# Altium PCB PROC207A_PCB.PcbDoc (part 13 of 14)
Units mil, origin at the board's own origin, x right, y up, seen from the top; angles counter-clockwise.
Board outline 4094.49 x 3724.79 mil, 8 copper layers (Top Layer, L2_GND1, L3_SIG1, L4_PWR1, L5_PWR2, L6_SIG2, L7_GND2, Bottom Layer), stack 58.1 mil thick; 584 components, 399 nets, 8440 pads, 5258 vias.
Unrouted connection lines stored in the file: 9.
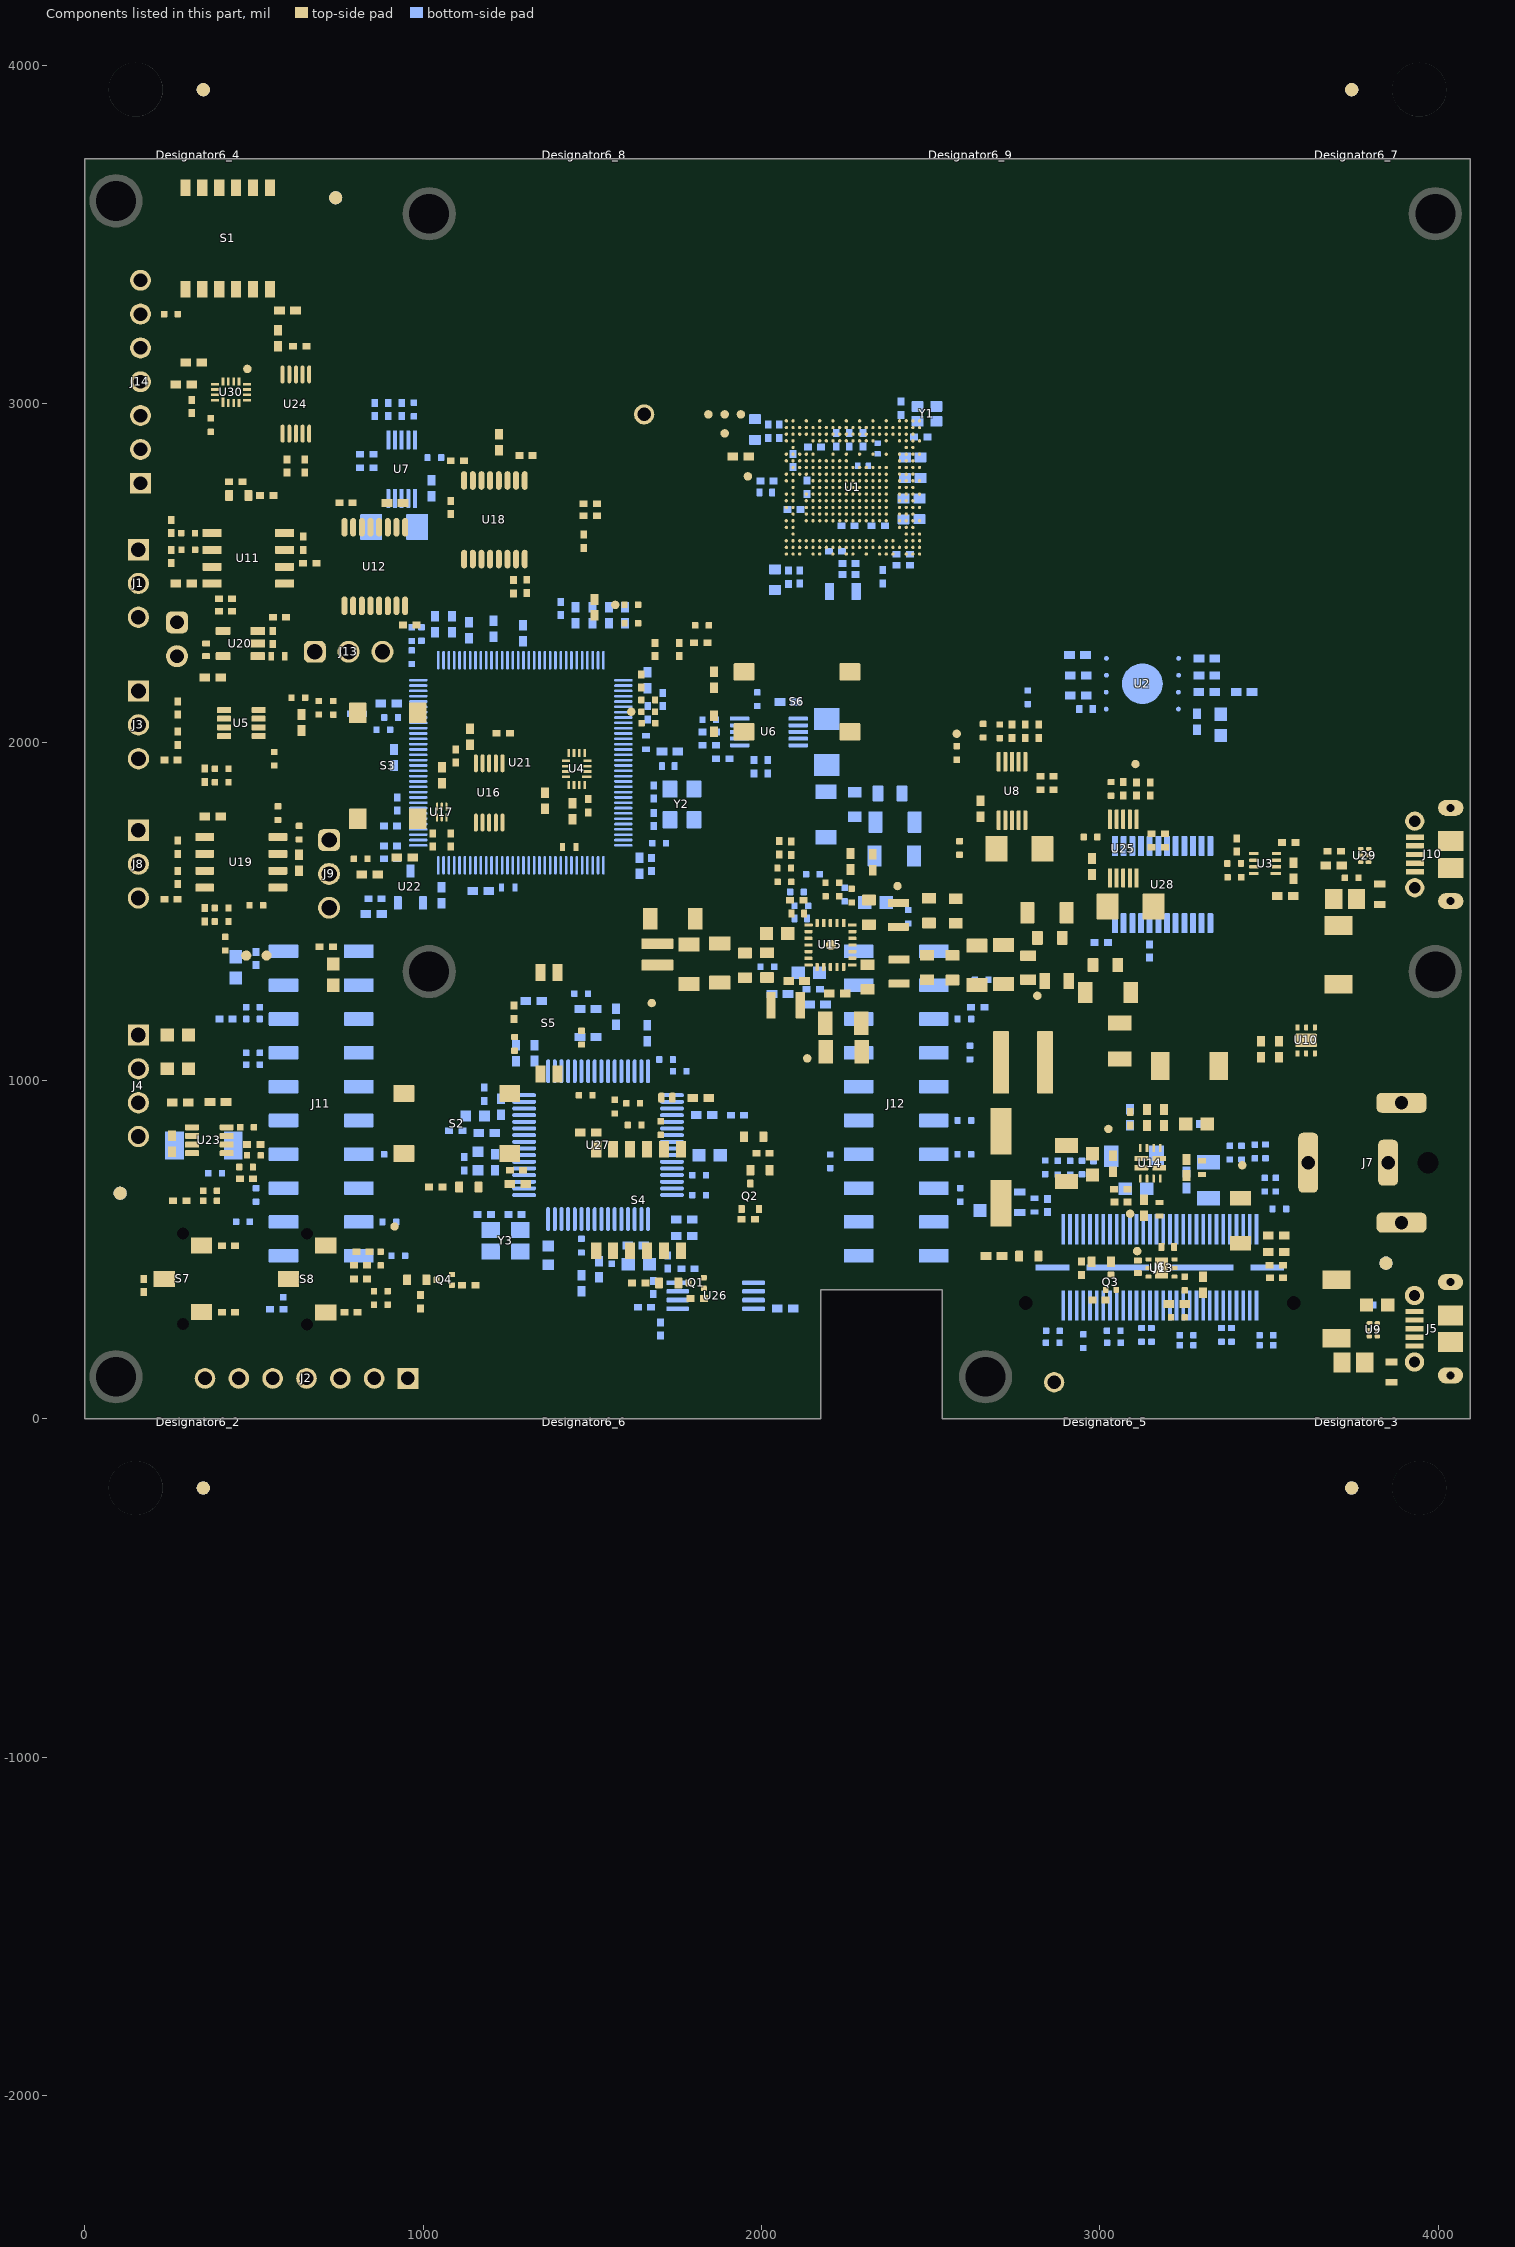
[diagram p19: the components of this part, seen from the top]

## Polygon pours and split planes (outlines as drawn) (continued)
NetC43_1 on Top Layer "NONET_L08_P-001" (solid, remove dead copper, pour order 55): 3167.19,1136 cw(c3167.19,1096.15) 3207.04,1096.15 3207.05,983.06 cw(c3183.73,983.06) 3183.73,959.75 2809.67,959.75 2809.67,1149.2 2981.83,1149.2 2995.03,1136
PMIC_B1_SW on Top Layer "NONET_L08_P-001" (solid, remove dead copper, pour order 63): 19 vertices, not listed, extent 2098.68,1183.02 2170.1,1345.39
VCC_CAN_3V3 on Top Layer "NONET_L08_P-001" (solid, remove dead copper, pour order 65): 1742.21,1383.92 1742.21,1508.92 1735.76,1515.37 1627.61,1515.37 1617.84,1505.6 1617.84,1390.27 1624.19,1383.92
PMIC_LS_3V3 on Top Layer "NONET_L08_P-001" (solid, remove dead copper, pour order 68): 18 vertices, not listed, extent 2107.76,1454.29 2200.61,1596.57
PMIC_OUT_3V3 on Top Layer "NONET_L08_P-001" (solid, remove dead copper, pour order 70): 2158.71,1458.43 2160.71,1456.43 2167.75,1456.43 2170.91,1459.59 2170.91,1478.69 2175.78,1483.56 2175.78,1498.59 2174.36,1500.01 2151.55,1500.01 2151.55,1488.94 2158.71,1481.78
REG_1V2 on Top Layer "NONET_L08_P-001" (solid, remove dead copper, pour order 72): 2766.65,1352.56 2835.87,1352.56 2855.88,1372.57 2855.88,1618.76 2870.17,1633.62 2870.17,1717.44 2862.09,1725.52 2800.91,1725.52 2789.73,1714.34 2789.73,1712.31 2762.36,1684.93 2762.36,1356.86
GND on Top Layer "NONET_L08_P-001" (solid, remove dead copper, pour order 74): 2871.13,1564.59 2881.18,1574.65 2913.66,1574.65 2923.57,1564.73 2923.57,1407.04 2913.53,1396.99 2877.48,1396.99 2871.13,1403.34
PMIC_OUT_1V8 on Top Layer "NONET_L08_P-001" (solid, remove dead copper, pour order 79): 2371.98,1572.31 2393.29,1593.62 2582.79,1593.62 2595.5,1580.91 2595.5,1512 2591.59,1508.09 2378.62,1508.09 2371.98,1514.73
VCC_3V3 on Top Layer "NONET_L08_P-001" (solid, remove dead copper, pour order 101): 2096.06,1522.91 2096.06,1556.94 2087.38,1565.63 2040.22,1565.63 2032.39,1557.8 2032.39,1532.06 2041.55,1522.91 2072.44,1522.91
RADAR_1V2 on Top Layer "NONET_L08_P-001" (solid, remove dead copper, pour order 102): 2646.67,1723.2 2726.68,1723.2 2728.66,1721.23 2728.66,1586.53 2715.74,1573.61 2650.99,1573.61 2638.29,1586.76 2638.29,1714.82
VCC_3V3 on Top Layer "NONET_L08_P-001" (solid, remove dead copper, pour order 103): 2706.44,1797.24 2705.05,1795.86 2635.98,1795.86 2629.83,1789.71 2629.83,1746.25 2635.35,1740.73 2705.06,1740.73
RADAR_1P2_RF on Top Layer "NONET_L08_P-001" (solid, remove dead copper, pour order 104): 2945.51,1538.73 2945.51,1473.66 2950.1,1469.08 3050.68,1469.08 3059.37,1477.76 3059.37,1548.73 3055.16,1552.94 2959.72,1552.94
VCC_3V3 on Top Layer "NONET_L08_P-001" (solid, remove dead copper, pour order 118): 3035.29,1627 3033.9,1625.61 2964.83,1625.61 2958.68,1619.46 2958.68,1576.01 2964.2,1570.48 3033.91,1570.48
RADAR_1V_RF_OUT on Top Layer "RADAR_1V_RF_OUT_L01_P234" (solid, remove dead copper, pour order 234): 2369.73,2821.14 ccw(c2369.73,2813.61) 2362.2,2813.61 2362.2,2773.89 ccw(c2369.98,2773.86) 2369.95,2766.07 ccw(c2370.06,2773.11) 2370.07,2766.07 2390.7,2766.07 ccw(c2390.7,2770.61) 2395.23,2770.61 ccw(c2389.92,2770.82) 2395.23,2770.83 2395.23,2815.73 ccw(c2389.82,2815.73) 2389.82,2821.14
RADAR_1V2 on Top Layer "RADAR_1V2_L01_P233" (solid, pour order 233): 2265.37,2777.9 2265.37,2649.78 2354.08,2649.78 2354.08,2777.9
RADAR_1P2_RF on Top Layer "RADAR_1P2_RF_L01_P232" (solid, pour order 232): 2396.98,2706.22 2393.74,2702.98 2362.11,2702.98 2362.37,2758.27 2393.93,2758.27 2396.98,2755.22
USB_5V on Top Layer "NONET_L08_P-001" (solid, remove dead copper, pour order 39): 3886.53,223.59 3873.62,210.68 3757.48,210.68 3757.48,133.67 3891.03,133.67 3900.21,142.85 3900.21,181.6 3925,206.39 3956.81,206.39 3956.81,223.59
VCC_3V3 on Top Layer "NONET_L08_P-001" (solid, remove dead copper, pour order 189): 1152.85,2008.86 1169.18,2025.19 1185.5,2025.19 1192.93,2017.76 1192.93,2008.23 1162.9,1978.2 1162.9,1911.54 1158.82,1907.46 1148.54,1907.46 1145.35,1913.04 1145.35,1949.34 1119.02,1975.67 1119.02,2001.9 1125.98,2008.86
PMIC_OUT_3V3 on Top Layer "NONET_L08_P-001" (solid, remove dead copper, pour order 169): 558.17,2266.41 489.05,2266.41 487.51,2264.87 487.51,2224.83 507.77,2204.57 563.68,2204.57 568.8,2209.69 568.8,2255.78
VBAT on Top Layer "NONET_L08_P-001" (solid, remove dead copper, pour order 148): 262.75,1053.2 249.66,1066.29 144.38,1066.29 126.57,1048.48 126.57,1020.61 144.41,1002.78 249.73,1002.78 262.75,1015.8
VSYS_IN on Top Layer "NONET_L08_P-001" (solid, remove dead copper, pour order 131): 262.75,1166 126.57,1166 126.57,1103.01 262.75,1103.01
5V_IN_USB on Top Layer "NONET_L08_P-001" (solid, remove dead copper, pour order 97): 3751.39,1390.15 cw(c3751.39,1372.52) 3769.03,1372.52 3769.03,1271.46 cw(c3748.83,1271.46) 3748.83,1251.25 3596.77,1251.25 cw(c3596.77,1291.03) 3557,1291.03 3557,1363 cw(c3584.15,1363) 3584.15,1390.15
NetC158_1 on Top Layer "NONET_L08_P-001" (solid, remove dead copper, pour order 82): 3775.21,1624.01 3764.13,1624.01 ccw(c3764.13,1603.61) 3743.73,1603.61 3743.73,1591.4 3736.52,1584.2 3704.55,1584.2 3699.92,1588.82 3699.92,1647.26 3704.39,1651.72 3776.84,1651.72 3778.02,1651.17 3778.45,1651.17 3779.29,1650.33 3779.29,1628.09
FTDI_VBUS on Top Layer "NONET_L08_P-001" (solid, remove dead copper, pour order 80): 20 vertices, not listed, extent 3733.04,1505.57 3931.5,1625.07
GND on L5_PWR2 "NONET_L08_P-001" (solid, remove dead copper, pour order 260): 2174.49,0 2174.49,381.95 2534.49,381.95 2534.49,0 4094.49,0 4094.49,3724.79 0,3724.79 0,0
VCC_XDS_3V3 on L5_PWR2 "VCC_XDS_3V3_L05_P250" (solid, pour order 250): 27 vertices, not listed, extent 1457.87,440.32 3434.04,1863.49
VCC_CAN_3V3 on L5_PWR2 "NONET_L08_P-001" (solid, remove dead copper, pour order 157): 24 vertices, not listed, extent 599.69,1434.67 1651.75,2166.54
VSYS_IN on L5_PWR2 "NONET_L08_P-001" (solid, remove dead copper, pour order 175): 20 vertices, not listed, extent 644.17,529.61 3242.79,1269.41
5V_IN_USB on L5_PWR2 "NONET_L08_P-001" (solid, remove dead copper, pour order 259): 17 vertices, not listed, extent 3290,396.63 3887,1392.37
RADAR_1P2_RF on L5_PWR2 "RADAR_1P2_RF_L05_P242" (solid, remove dead copper, pour order 242): 3000.38,2319.76 3127.26,2192.89 cw(c3056.55,2122.18) 3156.55,2122.18 3156.55,1570.55 3062.62,1476.62 2895.47,1476.62 2824.29,1547.81 2824.29,2018.29 ccw(c2724.29,2018.29) 2795,2089 2541,2343 2541,2461 2555.92,2475.92 2844.22,2475.92
RADAR_3V3 on L5_PWR2 "s" (solid, remove dead copper, pour order 237): 44 vertices, not listed, extent 951.28,2174 2356.49,2757.16
RADAR_1V_RF_OUT on L5_PWR2 "RADAR_1V_RF_OUT_L05_P240" (solid, remove dead copper, pour order 240): 1608,3037 cw(c1708,3037) 1708,3137 2493,3137 cw(c2493.5,3099.5) 2531,3100 2531,2834 cw(c2458.53,2834) 2458.53,2761.53 2276.8,2761.53 2240.06,2798.27 2240.05,2906.29 ccw(c2215.3,2906.25) 2215.26,2931 ccw(c2215.01,2913.76) 2214.93,2931 1664.19,2931 1627,2931 cw(c1627,2950) 1608,2950
RADAR_1V2 on L5_PWR2 "RADAR_1V2_L05_P243" (solid, remove dead copper, pour order 243): 2519.39,2368.97 2519.39,2303.82 ccw(c2619.39,2303.82) 2548.68,2233.11 2726.91,2054.89 cw(c2656.2,1984.18) 2756.2,1984.18 2756.2,1598.2 2739,1581 2607.1,1581 2583.47,1604.63 2583.47,1803.15 2222.48,2164.13 2222.48,2390.89 2285.14,2453.55 2434.81,2453.55
VCC_3V3 on L5_PWR2 "VCC_3V3_L05_P253" (solid, pour order 253): 31 vertices, not listed, extent 1042.12,1148.99 2095.15,2025.04
RADAR_1V2 on L5_PWR2 "RADAR_1V2_L05_P238" (solid, remove dead copper, pour order 238): 2049.85,2772.15 2049.85,2839.76 2134.86,2839.76 2146.98,2827.65 2146.98,2707.24 2124.05,2684.31 2073.04,2684.31 2073.04,2728.32 2076.96,2732.24 2077.43,2732.6 2082.14,2737.31 2082.14,2760.27 2070.26,2772.15
GND on L7_GND2 "NONET_L08_P-001" (solid, remove dead copper, pour order 204): 2174.49,0 2174.49,381.95 2534.49,381.95 2534.49,0 4094.49,0 4094.49,3724.79 0,3724.79 0,0
no net on Top Solder "NONET_L-01_P-001" (solid): 36 vertices, not listed, extent 1808.97,2271.38 4094.49,3724.79
GND on Bottom Layer "NONET_L08_P-001" (solid, remove dead copper, pour order 275): 2174.49,0 2174.49,381.95 2534.49,381.95 2534.49,0 4094.49,0 4094.49,3724.79 0,3724.79 0,0
VCC_3V3 on Bottom Layer "NONET_L08_P-001" (solid, remove dead copper, pour order 59): 464.12,1322.82 464.12,1261.5 455.57,1252.95 425.65,1252.95 420.7,1257.9 420.7,1316.8 426.72,1322.82
PMIC_OUT_1V8 on Bottom Layer "PMIC_OUT_1V8_L08_P262" (solid, remove dead copper, pour order 262): 2394.95,1874.32 2394.95,1823.02 2416.77,1801.2 2416.77,1561.58 2521.93,1561.58 2521.93,1686.07 2494.43,1713.57 2494.43,1841.57 2458.97,1877.03 2397.57,1877.03 2394.96,1874.42
MCU_3V3 on Bottom Layer "NONET_L-01_P-001" (solid, remove dead copper, pour order 272): 488.69,1368.69 515.66,1368.69 523.54,1360.82 630.36,1360.82 632.73,1363.18 632.73,1401.27 630,1404 426.3,1404 426.3,1344.92 464.92,1344.92
MCU_5V on Bottom Layer "NONET_L-01_P-001" (solid, remove dead copper, pour order 271): 748.34,1367.66 760,1356 850.8,1356 857.31,1362.51 857.31,1435.94 846.96,1446.3 760.94,1446.3 748.34,1433.7
PMIC_VREG_5V0 on Bottom Layer "NONET_L08_P-001" (solid, remove dead copper, pour order 126): 2151.57,1349.58 2151.57,1286.47 2158.71,1279.32 2158.71,1259.64 2161.3,1257.06 2181.58,1257.06 2215.51,1290.99 2215.69,1290.99 2232.59,1307.89 2232.59,1349.58
VCC_3V3 on Bottom Layer "NONET_L-01_P-001" (solid, remove dead copper, pour order 90): 3227.86,2105.87 ccw(c3227.86,2098.4) 3222.57,2103.68 ccw(c3228.46,2097.79) 3220.13,2097.79 3220.13,2097.54 ccw(c3227.26,2097.54) 3222.22,2092.5 3246.44,2068.28 3299.72,2068.28 3304.78,2063.22 3401.59,2063.22 3401.59,2105.87 3293.62,2105.87
VCC_3V3 on Bottom Layer "NONET_L08_P-001" (solid, remove dead copper, pour order 229): 808.63,2763.01 cw(c825.05,2763.01) 825.05,2779.42 886.95,2779.42 902.6,2763.77 902.6,2614.43 cw(c881.35,2614.43) 881.35,2593.19 815.74,2593.19 cw(c815.74,2600.29) 808.63,2600.29
RADAR_1V2 on Bottom Layer "RADAR_1V2_L08_P255" (solid, remove dead copper, pour order 255): 2263.04,2405.96 ccw(c2272.94,2406.02) 2273,2396.12 2338.15,2396.12 2338.15,2650.39 2353.14,2665.38 2353.14,2761.69 2340.4,2774.43 2296.17,2774.43 2270.38,2774.43 2263.04,2767.08 2263.04,2607.99 2266.87,2604.25 2266.87,2579.12 2263.04,2575.28
RADAR_1V_RF_OUT on Bottom Layer "RADAR_1V_RF_OUT_L08_P246" (solid, remove dead copper, pour order 246): 2400.6,2819.58 2358.56,2819.58 2358.56,2764.98 2377.61,2765.29 2488.11,2765.29 2488.11,2798.53 2421.65,2798.53
FTDI_3V3 on Bottom Layer "NONET_L08_P-001" (solid, remove dead copper, pour order 226): 1470.92,1183.7 1436.51,1183.7 1428.33,1175.52 1428.33,1103.09 1420.76,1095.52 1420.76,995.73 1425.18,991.3 1430.66,991.3 1435.97,996.62 1435.97,1061.27 1479.03,1104.32 1479.03,1175.59
RADAR_1V8 on Bottom Layer "RADAR_1V8_L08_P267" (solid, remove dead copper, pour order 267): 2155.36,2036.43 2153.54,2038.25 2153.54,2122.54 2165,2134 2226,2134 2238,2122 2238,2041.31 2233.11,2036.43
RADAR_1V8 on Bottom Layer "RADAR_1V8_L08_P261" (solid, remove dead copper, pour order 261): 2011.29,2919.66 1933.01,2919.66 1933.01,2844.69 2061.56,2844.69 2093.15,2876.28 2093.15,2897.94 2073.91,2917.18 2013.76,2917.18
REG_1V8 on Bottom Layer "REG_1V8_L08_P108" (solid, remove dead copper, pour order 108): 2365.66,1877.35 2365.66,1821.94 2359.72,1816 2163.79,1816 2152.17,1827.63 2152.17,1965.56 2276.9,1965.56 2365.12,1877.35
VCC_3V3 on Bottom Layer "NONET_L08_P-001" (solid, remove dead copper, pour order 133): 2138.11,2067.98 2138.11,2125.66 2131.06,2132.71 2085.91,2132.71 2085.91,2109.08 2079.71,2102.89 2079.71,2067.48 2083.21,2063.98 2134.11,2063.98
RADAR_1P2_RF on Bottom Layer "RADAR_1P2_RF_L08_P087" (solid, remove dead copper, pour order 87): 2652.16,2422.03 2632.48,2402.36 2590.96,2402.36 2559.81,2433.51 2559.81,2471.41 2570.84,2482.44 2570.84,2641.3 2520.53,2691.61 2405.6,2691.61 2397.78,2699.89 2359.44,2699.89 2359.44,2754.78 2558.22,2754.78 2652.16,2660.84
VSYS_IN on Bottom Layer "NONET_L08_P-001" (solid, remove dead copper, pour order 124): 3233.18,711.96 cw(c3238.72,706.42) 3238.72,714.25 3343.24,714.25 ccw(c3343.24,729.32) 3358.32,729.32 3358.32,773.96 ccw(c3345.68,773.96) 3345.68,786.59 3212.6,786.59 3198.2,772.19 3198.2,711.97 3205.09,705.08 3219.82,705.08 ccw(c3219.82,720.73) 3230.89,709.66
VCC_XDS_3V3 on Bottom Layer "NONET_L08_P-001" (solid, remove dead copper, pour order 199): 1713.14,495.24 1732.82,495.24 1758.48,520.9 1824.18,520.9 1833.68,511.39 1889.78,511.39 1897.66,503.52 1897.66,492.69 1890.77,485.8 1826.6,485.8 1810.8,501.6 1777.29,501.6 1747.3,471.61 1713.14,471.61
FTDI_3V3 on Bottom Layer "NONET_L08_P-001" (solid, remove dead copper, pour order 225): 22 vertices, not listed, extent 1159.79,967.55 1347.39,1203.32
FTDI_3V3 on Bottom Layer "NONET_L08_P-001" (solid, remove dead copper, pour order 227): 42 vertices, not listed, extent 1628.45,760.83 2005.92,1177.58
FTDI_3V3 on Bottom Layer "NONET_L08_P-001" (solid, remove dead copper, pour order 228): 60 vertices, not listed, extent 1519.73,212.54 2062.13,656.03
VCC_3V3 on Bottom Layer "NONET_L08_P-001" (solid, remove dead copper, pour order 117): 2095.15,1566.42 2092.88,1568.69 2074.89,1568.69 2040.35,1568.69 2028.05,1556.39 2028.05,1536.84 2034.16,1530.73 2078.08,1530.73 2095.15,1547.8
PMIC_OUT_3V3 on Bottom Layer "NONET_L08_P-001" (solid, remove dead copper, pour order 178): 2116.03,1572.67 2110.47,1567.1 2110.47,1540.38 2117.19,1533.66 2146.43,1533.66 2148.12,1531.97 2170.24,1531.97 2177.92,1539.65 2177.92,1567.35 2172.61,1572.67
VSYS_IN on Bottom Layer "NONET_L08_P-001" (solid, remove dead copper, pour order 125): 3014.01,809.46 3011.91,807.36 3011.91,741.03 3014.95,738.07 3014.95,679.49 3033.36,661.08 3095.07,661.08 3095.07,698.48 3101.21,704.63 3101.21,804.6 3096.35,809.46
PMIC_OUT_3V3 on Bottom Layer "NONET_L08_P-001" (solid, remove dead copper, pour order 116): 2173.82,1470.27 2173.82,1488.83 2165.97,1496.68 2127.66,1496.68 2122.66,1491.68 2122.66,1471.46 2130.75,1463.37 2165.97,1463.37
PMIC_OUT_3V3 on Bottom Layer "NONET_L08_P-001" (solid, remove dead copper, pour order 143): 2334.39,1446.71 2334.39,1471.3 2324.08,1481.61 2324.08,1489.79 2331.92,1497.63 2370.34,1497.63 2377.61,1490.36 2381.33,1486.78 2381.33,1449 2371.6,1439.26 2341.83,1439.26
PMIC_OUT_3V3 on Bottom Layer "NONET_L08_P-001" (solid, remove dead copper, pour order 144): 2326.85,1360.7 2316.08,1349.94 2316.08,1313.79 2323.83,1306.03 2365.25,1306.03 2374.98,1315.77 2374.98,1353.55 2367.54,1360.7
CONN_5V on Bottom Layer "NONET_L08_P-001" (solid, remove dead copper, pour order 179): 22 vertices, not listed, extent 2689.36,290.17 2917.43,640.11
VSYS_IN on Bottom Layer "NONET_L08_P-001" (solid, remove dead copper, pour order 180): 2652.97,546.88 ccw(c2652.97,559.66) 2665.74,559.66 2665.74,634.63 2623.06,634.63 ccw(c2623.06,620.77) 2609.2,620.77 2609.2,561.59 ccw(c2623.9,561.59) 2623.9,546.88
RADAR_1V8 on Bottom Layer "RADAR_1V8_L08_P245" (solid, remove dead copper, pour order 245): 1999.18,2533.13 2050.33,2533.13 2068.31,2551.11 2088.11,2551.11 2093.74,2545.48 2093.74,2496.29 2008.97,2496.29 1999.18,2506.08
RADAR_3V3 on Bottom Layer "RADAR_3V3_L08_P244" (solid, remove dead copper, pour order 244): 2022.92,2739.04 2022.92,2749.11 2030.23,2756.43 2073.27,2756.43 2073.27,2728.44 2070.86,2726.03 2023.27,2726.03
RADAR_1V8 on Bottom Layer "RADAR_1V8_L08_P230" (solid, remove dead copper, pour order 230): 2064.55,2762.56 2068.18,2766.18 2068.18,2779 2064.92,2782.24 2020.18,2782.24 2020.18,2762.56
VCC_XDS_3V3 on Bottom Layer "NONET_L-01_P-001" (solid, remove dead copper, pour order 146): 30 vertices, not listed, extent 1117.6,2150.2 1351.5,2319.21
VCC_XDS_3V3 on Bottom Layer "NONET_L08_P-001" (solid, remove dead copper, pour order 177): 44 vertices, not listed, extent 1037.38,1501.76 1481.43,1738.77
RADAR_3V3 on Bottom Layer "NONET_L08_P-001" (solid, remove dead copper, pour order 135): 1029.85,2663.11 1018.17,2674.79 948.18,2674.79 937.43,2664.03 937.43,2580.56 957.41,2560.58 1020.82,2560.58 1029.85,2569.61
VCC_XDS_3V3 on Bottom Layer "NONET_L-01_P-001" (solid, remove dead copper, pour order 176): 25 vertices, not listed, extent 847.35,1777.88 1016.3,1949.03
VCC_3V3 on Bottom Layer "NONET_L08_P-001" (solid, remove dead copper, pour order 142): 969.86,2746.2 973.89,2750.24 1011.64,2750.24 1015.67,2746.2 1033.37,2746.2 1036.87,2742.71 1036.87,2691.81 1030.06,2685 978,2685 969.86,2693.15
VBUS_1_DETECT on Bottom Layer "NONET_L08_P-001" (solid, remove dead copper, pour order 112): 934.67,1762.86 934.67,1711.25 946.69,1699.23 1009.04,1699.23 1011.17,1699.23 1012.98,1697.42 1012.98,1685.84 1006.67,1679.53 948.83,1679.53 934.67,1665.38 934.67,1645.69 911.05,1645.69 910.55,1646.19 910.55,1762.86
VCC_XDS_3V3 on Bottom Layer "NONET_L08_P-001" (solid, remove dead copper, pour order 187): 956.09,2124.36 952.35,2128.1 907.43,2128.1 905.78,2126.44 905.78,2102.24 929.99,2102.24 947.27,2084.95 1010.83,2084.95 1015.74,2089.86 1015.74,2122.52 1008.98,2124.36
GND on L2_GND1 "NONET_L08_P-001" (solid, remove dead copper, pour order 268): 2174.49,0 2174.49,381.95 2534.49,381.95 2534.49,0 4094.49,0 4094.49,3724.79 0,3724.79 0,0
GND on L3_SIG1 "NONET_L08_P-001" (solid, remove dead copper, pour order 258): 2174.49,0 2174.49,381.95 2534.49,381.95 2534.49,0 4094.49,0 4094.49,3724.79 0,3724.79 0,0
GND on L6_SIG2 "NONET_L08_P-001" (solid, remove dead copper, pour order 263): 2174.49,0 2174.49,381.95 2534.49,381.95 2534.49,0 4094.49,0 4094.49,3724.79 0,3724.79 0,0

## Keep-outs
Keep-Out Layer:
  circle w1: c3970.44,757.12 r42.44
  circle w1: c3573.95,342.53 r35
  circle w1: c2781.43,342.53 r35
  text ".Layer_Name" at 186.57,-874.24 h60

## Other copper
Top Layer:
  pour cut-out: 2112.84,2920.57 cw(c2112.84,2930.41) 2103,2930.41 cw(c2112.84,2930.41) 2112.84,2940.25 cw(c2112.84,2930.41) 2122.68,2930.41 cw(c2112.84,2930.41)
  pour cut-out: 2447.49,2881.2 cw(c2447.49,2871.36) 2457.33,2871.36 cw(c2447.49,2871.36) 2447.49,2861.51 cw(c2447.49,2871.36) 2437.64,2871.36 cw(c2447.49,2871.36)
  pour cut-out: 2447.49,2644.98 cw(c2447.49,2635.14) 2457.33,2635.14 cw(c2447.49,2635.14) 2447.49,2625.29 cw(c2447.49,2635.14) 2437.64,2635.14 cw(c2447.49,2635.14)
  pour cut-out: 2437.64,2674.51 cw(c2447.49,2674.51) 2447.49,2684.35 cw(c2447.49,2674.51) 2457.33,2674.51 cw(c2447.49,2674.51) 2447.49,2664.66 cw(c2447.49,2674.51)
  pour cut-out: 2437.64,2713.88 cw(c2447.49,2713.88) 2447.49,2723.72 cw(c2447.49,2713.88) 2457.33,2713.88 cw(c2447.49,2713.88) 2447.49,2704.03 cw(c2447.49,2713.88)
  pour cut-out: 2437.64,2753.25 cw(c2447.49,2753.25) 2447.49,2763.09 cw(c2447.49,2753.25) 2457.33,2753.25 cw(c2447.49,2753.25) 2447.49,2743.4 cw(c2447.49,2753.25)
  pour cut-out: 2437.64,2792.62 cw(c2447.49,2792.62) 2447.49,2802.46 cw(c2447.49,2792.62) 2457.33,2792.62 cw(c2447.49,2792.62) 2447.49,2782.77 cw(c2447.49,2792.62)
  pour cut-out: 2437.64,2831.99 cw(c2447.49,2831.99) 2447.49,2841.83 cw(c2447.49,2831.99) 2457.33,2831.99 cw(c2447.49,2831.99) 2447.49,2822.14 cw(c2447.49,2831.99)
  pour cut-out: 2437.64,2910.73 cw(c2447.49,2910.73) 2447.49,2920.57 cw(c2447.49,2910.73) 2457.33,2910.73 cw(c2447.49,2910.73) 2447.49,2900.88 cw(c2447.49,2910.73)
  pour cut-out: 2152.21,2920.57 cw(c2152.21,2930.41) 2142.37,2930.41 cw(c2152.21,2930.41) 2152.21,2940.25 cw(c2152.21,2930.41) 2162.05,2930.41 cw(c2152.21,2930.41)
  pour cut-out: 2230.95,2920.57 cw(c2230.95,2930.41) 2221.11,2930.41 cw(c2230.95,2930.41) 2230.95,2940.25 cw(c2230.95,2930.41) 2240.79,2930.41 cw(c2230.95,2930.41)
  pour cut-out: 2191.58,2920.57 cw(c2191.58,2930.41) 2181.74,2930.41 cw(c2191.58,2930.41) 2191.58,2940.25 cw(c2191.58,2930.41) 2201.42,2930.41 cw(c2191.58,2930.41)
  pour cut-out: 2309.69,2920.57 cw(c2309.69,2930.41) 2299.85,2930.41 cw(c2309.69,2930.41) 2309.69,2940.25 cw(c2309.69,2930.41) 2319.53,2930.41 cw(c2309.69,2930.41)
  pour cut-out: 2270.32,2920.57 cw(c2270.32,2930.41) 2260.48,2930.41 cw(c2270.32,2930.41) 2270.32,2940.25 cw(c2270.32,2930.41) 2280.16,2930.41 cw(c2270.32,2930.41)
  pour cut-out: 2349.06,2920.57 cw(c2349.06,2930.41) 2339.22,2930.41 cw(c2349.06,2930.41) 2349.06,2940.25 cw(c2349.06,2930.41) 2358.9,2930.41 cw(c2349.06,2930.41)
  pour cut-out: 2388.43,2920.57 cw(c2388.43,2930.41) 2378.59,2930.41 cw(c2388.43,2930.41) 2388.43,2940.25 cw(c2388.43,2930.41) 2398.27,2930.41 cw(c2388.43,2930.41)
  pour cut-out: 3468.43,2318.16 3228.48,2318.16 3228.48,2375.84 3185.62,2375.84 3185.62,2392.11 3228.48,2392.11 3228.48,2459.1 3326.12,2459.1 3326.12,2473.48 3283.26,2473.48 3283.26,2489.75 3326.12,2489.75 3326.12,2504.12 3228.48,2504.12 3228.48,2571.12 3185.62,2571.12 3185.62,2587.38 3228.48,2587.38 3228.48,2654.38 3326.12,2654.38 3326.12,2668.75 3283.26,2668.75 3283.26,2685.02 3326.12,2685.02 3326.12,2699.4 3228.48,2699.4 3228.48,2766.39 3185.62,2766.39 3185.62,2782.66 3228.48,2782.66 3228.48,2849.65 3326.12,2849.65 3326.12,2864.03 3283.26,2864.03 3283.26,2880.3 3326.12,2880.3 3326.12,2894.67 3228.48,2894.67 3228.48,2961.67 3185.62,2961.67 3185.62,2977.93 3228.48,2977.93 3228.48,3044.93 3326.12,3044.93 3326.12,3059.3 3283.26,3059.3 3283.26,3075.57 3326.12,3075.57 3326.12,3136.34 3468.43,3136.34
  region net TX1: 3283.26,3063.25 3283.26,3071.63 3314.31,3071.63 3314.31,3067.18 3330.06,3067.18 3330.06,3092.32 3360.97,3092.32 3360.97,3087.4 3384.2,3087.4 3384.2,3036.59 3353.29,3036.59 3353.29,3041.51 3330.06,3041.51 3330.06,3063.25
  region net TX2: 3185.62,2965.61 3185.62,2973.99 3216.68,2973.99 3216.68,2969.55 3232.42,2969.55 3232.42,2994.68 3263.33,2994.68 3263.33,2989.76 3286.56,2989.76 3286.56,2938.95 3255.65,2938.95 3255.65,2943.88 3232.42,2943.88 3232.42,2965.61
  region net TX3: 3283.26,2867.97 3283.26,2876.36 3314.31,2876.36 3314.31,2871.91 3330.06,2871.91 3330.06,2897.05 3360.97,2897.05 3360.97,2892.12 3384.2,2892.12 3384.2,2841.32 3353.29,2841.32 3353.29,2846.24 3330.06,2846.24 3330.06,2867.97
  region net TX4: 3185.62,2770.33 3185.62,2778.72 3216.68,2778.72 3216.68,2774.27 3232.42,2774.27 3232.42,2799.41 3263.33,2799.41 3263.33,2794.49 3286.56,2794.49 3286.56,2743.68 3255.65,2743.68 3255.65,2748.6 3232.42,2748.6 3232.42,2770.33
  region net TX8: 3185.62,2379.78 3185.62,2388.17 3216.67,2388.17 3216.67,2383.72 3232.42,2383.72 3232.42,2408.86 3263.33,2408.86 3263.33,2403.94 3286.55,2403.94 3286.55,2353.13 3255.65,2353.13 3255.65,2358.05 3232.42,2358.05 3232.42,2379.78
  region net TX7: 3283.26,2477.42 3283.26,2485.8 3314.31,2485.8 3314.31,2481.36 3330.06,2481.36 3330.06,2506.49 3360.97,2506.49 3360.97,2501.57 3384.2,2501.57 3384.2,2450.77 3353.29,2450.77 3353.29,2455.69 3330.06,2455.69 3330.06,2477.42
  region net TX6: 3185.62,2575.06 3185.62,2583.44 3216.67,2583.44 3216.67,2578.99 3232.42,2578.99 3232.42,2604.13 3263.33,2604.13 3263.33,2599.21 3286.56,2599.21 3286.56,2548.4 3255.65,2548.4 3255.65,2553.32 3232.42,2553.32 3232.42,2575.06
  region net TX5: 3283.26,2672.69 3283.26,2681.08 3314.31,2681.08 3314.31,2676.63 3330.06,2676.63 3330.06,2701.77 3360.97,2701.77 3360.97,2696.85 3384.19,2696.85 3384.19,2646.04 3353.29,2646.04 3353.29,2650.96 3330.06,2650.96 3330.06,2672.69
  pour cut-out: 2837.46,1149.2 2837.46,1183.48 2712.68,1183.48 2712.68,1149.2
  pour cut-out: 2095.38,1252.53 2060.43,1252.53 2060.43,1169.16 2095.38,1169.16
  pour cut-out: 2375.31,1505.83 2375.31,1470.87 2458.68,1470.87 2458.68,1505.83
  region net RX8: 2627.71,3505.92 2627.71,3513.79 2623.26,3513.79 2623.26,3539.07 2619.33,3539.07 2619.33,3517.73 2601.24,3517.73 2601.24,3513.79 2565.41,3513.79 2565.41,3561.98 2583.5,3561.98 2583.5,3565.92 2619.33,3565.92 2619.33,3543 2627.2,3543 2627.2,3539.07 2631.65,3539.07 2631.65,3455.15 2623.26,3455.15 2623.26,3505.92
  region net RX7: 2530.07,3505.92 2530.07,3513.79 2525.63,3513.79 2525.63,3539.07 2521.69,3539.07 2521.69,3517.73 2503.6,3517.73 2503.6,3513.79 2467.77,3513.79 2467.77,3561.98 2485.86,3561.98 2485.86,3565.92 2521.69,3565.92 2521.69,3543 2529.56,3543 2529.56,3539.07 2534.01,3539.07 2534.01,3455.15 2525.63,3455.15 2525.63,3505.92
  region net RX6: 2432.44,3505.92 2432.44,3513.79 2427.99,3513.79 2427.99,3539.07 2424.05,3539.07 2424.05,3517.73 2405.96,3517.73 2405.96,3513.79 2370.13,3513.79 2370.13,3561.98 2388.22,3561.98 2388.22,3565.92 2424.05,3565.92 2424.05,3543 2431.92,3543 2431.92,3539.07 2436.37,3539.07 2436.37,3455.15 2427.99,3455.15 2427.99,3505.92
  region net RX5: 2334.8,3505.92 2334.8,3513.79 2330.35,3513.79 2330.35,3539.07 2326.41,3539.07 2326.41,3517.73 2308.32,3517.73 2308.32,3513.79 2272.5,3513.79 2272.5,3561.98 2290.59,3561.98 2290.59,3565.92 2326.41,3565.92 2326.41,3543 2334.29,3543 2334.29,3539.07 2338.74,3539.07 2338.74,3455.15 2330.35,3455.15 2330.35,3505.92
  region net RX4: 2166.47,3505.92 2166.47,3513.79 2170.92,3513.79 2170.92,3539.07 2174.86,3539.07 2174.86,3517.73 2192.95,3517.73 2192.95,3513.79 2228.77,3513.79 2228.77,3561.98 2210.68,3561.98 2210.68,3565.92 2174.86,3565.92 2174.86,3543 2166.98,3543 2166.98,3539.07 2162.53,3539.07 2162.53,3455.15 2170.92,3455.15 2170.92,3505.92
  region net GND: 2605.17,3509.85 2605.17,3513.79 2610.1,3513.79 2610.11,3513.79
  region net GND: 2507.53,3509.85 2507.53,3513.79 2512.46,3513.79 2512.47,3513.79
  region net GND: 2450.27,3510.25 2450.27,3513.79 2446.73,3513.79
  region net GND: 2409.9,3509.85 2409.9,3513.79 2414.82,3513.79 2414.83,3513.79
  region net GND: 2312.26,3509.85 2312.26,3513.79 2317.19,3513.79
  region net GND: 2091.37,3509.85 2091.37,3513.79 2086.45,3513.79 2086.44,3513.79
  region net GND: 1993.74,3509.85 1993.74,3513.79 1988.81,3513.79 1988.8,3513.79
  region net GND: 1896.1,3509.85 1896.1,3513.79 1891.17,3513.79 1891.16,3513.79
  region net RX1: 1873.56,3505.92 1873.56,3513.79 1878.01,3513.79 1878.01,3539.07 1881.94,3539.07 1881.94,3517.73 1900.03,3517.73 1900.03,3513.79 1935.86,3513.79 1935.86,3561.98 1917.77,3561.98 1917.77,3565.92 1881.94,3565.92 1881.94,3543 1874.07,3543 1874.07,3539.07 1869.62,3539.07 1869.62,3455.15 1878.01,3455.15 1878.01,3505.92
  region net RX2: 1971.2,3505.92 1971.2,3513.79 1975.64,3513.79 1975.64,3539.07 1979.58,3539.07 1979.58,3517.73 1997.67,3517.73 1997.67,3513.79 2033.5,3513.79 2033.5,3561.98 2015.41,3561.98 2015.41,3565.92 1979.58,3565.92 1979.58,3543 1971.71,3543 1971.71,3539.07 1967.26,3539.07 1967.26,3455.15 1975.64,3455.15 1975.64,3505.92
  region net RX3: 2068.83,3505.92 2068.83,3513.79 2073.28,3513.79 2073.28,3539.07 2077.22,3539.07 2077.22,3517.73 2095.31,3517.73 2095.31,3513.79 2131.14,3513.79 2131.14,3561.98 2113.05,3561.98 2113.05,3565.92 2077.22,3565.92 2077.22,3543 2069.35,3543 2069.35,3539.07 2064.9,3539.07 2064.9,3455.15 2073.28,3455.15 2073.28,3505.92
  pour cut-out: 1865.68,3455.15 1881.94,3455.15 1881.94,3513.79 1896.1,3513.79 1896.1,3509.85 1953.36,3509.85 1953.36,3513.79 1963.32,3513.79 1963.32,3455.15 1979.58,3455.15 1979.58,3513.79 1993.74,3513.79 1993.74,3509.85 2051,3509.85 2051,3513.79 2060.96,3513.79 2060.96,3455.15 2077.22,3455.15 2077.22,3513.79 2091.37,3513.79 2091.37,3509.85 2148.64,3509.85 2148.64,3513.79 2158.6,3513.79 2158.6,3455.15 2174.86,3455.15 2174.86,3513.79 2189.01,3513.79 2189.01,3509.85 2312.26,3509.85 2312.26,3513.79 2326.41,3513.79 2326.41,3455.15 2342.67,3455.15 2342.67,3513.79 2352.63,3513.79 2352.63,3509.85 2409.9,3509.85 2409.9,3513.79 2424.05,3513.79 2424.05,3455.15 2440.31,3455.15 2440.31,3513.79 2450.27,3513.79 2450.27,3509.85 2507.53,3509.85 2507.53,3513.79 2521.69,3513.79 2521.69,3455.15 2537.95,3455.15 2537.95,3513.79 2547.91,3513.79 2547.91,3509.85 2605.17,3509.85 2605.17,3513.79 2619.33,3513.79 2619.33,3455.15 2635.59,3455.15 2635.59,3513.79 2645.54,3513.79 2645.54,3593.2 1855.73,3593.2 1855.73,3513.79 1865.68,3513.79
  text ".Layer_Name" at 186.57,-874.24 h60
L2_GND1:
  text ".Layer_Name" at 186.57,-874.24 h60
L3_SIG1:
  text ".Layer_Name" at 186.57,-874.24 h60
L5_PWR2:
  text ".Layer_Name" at 186.57,-874.24 h60
L7_GND2:
  text ".Layer_Name" at 186.57,-874.24 h60
L4_PWR1:
  text ".Layer_Name" at 186.57,-874.24 h60
L6_SIG2:
  text ".Layer_Name" at 186.57,-874.24 h60
Bottom Layer:
  pour cut-out: 2382.6,2858.93 2382.6,2827.96 2395.82,2814.74 2493.74,2814.74 2495.5,2816.5 2493,2819 2397.76,2819 2385.71,2831.05 2385.71,2857.56 2399.94,2871.79 2482.21,2871.79 2493,2861 2493,2819 2495.5,2816.5 2498,2819 2498,2861.7 2484.13,2875.58 2399.25,2875.58
  pour cut-out: 2328.5,2848.36 2328.5,2886.5 2164.38,2886.5 2164.38,2834.77 2250.55,2834.77 2264.15,2848.36
  text ".Layer_Name" at 186.57,-874.24 h60

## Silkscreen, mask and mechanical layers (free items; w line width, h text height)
Top Overlay:
  circle w8.39: c3055.84,465.42 r3.16
  circle w11.62: c1513.17,440.12 r4.92
  circle w11.62: c1510.62,1896.82 r0.98
  circle w11.62: c1105.66,2504.93 r0.98
  circle w11.62: c643.63,2462.87 r4.92
  circle w11.62: c732.13,2404.86 r4.92
  circle w11.62: c406.28,2974.31 r4.92
  circle w11.62: c585.23,2873.27 r4.92
  circle w11.62: c546.89,3684.86 r4.92
  circle w11.62: c1154.53,1718.51 r0.98
  circle w2.07: c714.84,1128.73 r13
  region: 2456.98,2989.02 2477.36,2989.02 2467.17,2978.83
  region: 734.71,358.39 746.64,346.46 734.71,346.46
  region: 375.36,359.15 387.29,347.22 375.36,347.22
  region: 1047.6,1753.58 1033.99,1753.58 1040.8,1760.38
  region: 3801.19,1627.46 3787.57,1627.46 3794.38,1634.27
  region: 3550.04,1618.62 3550.04,1605 3543.24,1611.81
  region: 3123.51,480.39 3133.14,490.01 3133.14,480.39
  region: 3790.26,300.77 3803.87,300.77 3797.07,293.96
  region: 3216.11,750.75 3216.11,737.14 3209.3,743.95
  region: 3627.22,1176.82 3644.09,1176.82 3635.66,1168.39
  lines w0.52: 703.89,1119.41 642.99,1098.8 703.89,1119.41 ; 703.89,1119.41 646.82,1091.14 703.89,1119.41
  lines w1.04: 700.06,1117.76 693.12,1115.37 700.06,1117.76 ; 700.06,1117.76 692.71,1114.44 700.06,1117.76
  lines w2.07: 692.71,1114.75 644.34,1098.28 692.71,1114.75 ; 692.71,1114.75 646.31,1092.17 692.71,1114.75
  lines w4.14: 651.9,1096.63 647.76,1098.08 651.9,1096.63 ; 651.9,1096.63 642.47,1093.21 651.9,1096.63 ; 546.25,1137.02 551.95,1139.92 546.25,1137.02 ; 646.1,1095.69 676.34,1107.92 646.1,1095.69
  lines w6: 291.65,2648.09 303.65,2635.02 ; 303.65,2669 303.65,2635.02 ; 315.65,2648.09 303.65,2635.02 ; 329.38,1417 329.38,1534.75 364,1534.75 ; 439,1445.54 459.49,1445.54 459.49,1534.75 441,1534.75 ; 2172.58,1735 2172.58,1624 ; 2185,1502.33 2172.58,1502.33 2172.58,1624 ; 2212,1624 2172.58,1624 ; 2246.33,1584.98 2290.91,1584.98 ; 2559.5,886 2590.5,886 ; 2575,870.5 2575,901.5 ; 209,1300 370,1300 370,1417 209,1417 209,1406 209,1300 ; 2110,1735 2253,1735 2253,1835 2110,1835 2110,1813 2110,1735
  lines w9.32: 507.1,1102.01 512.8,1107.81 ; 507.1,1102.01 512.8,1107.81 ; 507.1,1102.01 498.4,1092.38 507.1,1102.01 ; 512.8,1107.81 517.98,1112.78 ; 512.8,1107.81 517.98,1112.78 ; 517.98,1112.78 520.67,1115.37 ; 517.98,1112.78 520.67,1115.37 ; 520.67,1115.37 526.88,1120.34 ; 520.67,1115.37 526.88,1120.34 ; 526.88,1120.34 532.68,1125.11 ; 526.88,1120.34 532.68,1125.11 ; 532.68,1125.11 534.96,1126.66 ; 532.68,1125.11 534.96,1126.66 ; 534.96,1126.66 537.66,1128.32 ; 534.96,1126.66 537.66,1128.32 ; 537.66,1128.32 541.9,1131.01 537.66,1128.32 ; 547.29,1134.74 537.24,1128.32 547.29,1134.74 ; 547.29,1134.74 536.83,1128.22 547.29,1134.74 ; 554.75,1102.94 ccw(c560.47,1098.58) 565,1093 ; 554.75,1102.94 ccw(c560.47,1098.58) 565,1093 ; 554.75,1102.94 574.94,1129.46 554.75,1102.94 ; 559.2,1140.54 552.36,1137.23 559.2,1140.54 ; 559.2,1140.54 564.48,1142.72 ; 559.2,1140.54 564.48,1142.72 ; 564.48,1142.72 cw(c569.16,1132.76) 574.63,1142.3 ; 564.48,1142.72 cw(c569.16,1132.76) 574.63,1142.3 ; 565,1093 cw(c714.06,833.24) 626.42,1119.62 ; 565,1093 cw(c714.06,833.24) 626.42,1119.62 ; 574.63,1142.3 cw(c572.35,1138.33) 576.81,1139.4 ; 574.63,1142.3 cw(c572.35,1138.33) 576.81,1139.4 ; 576.81,1139.4 cw(c564.81,1136.51) 574.94,1129.46 ccw(c564.81,1136.51) 576.81,1139.4 ; 626.42,1119.62 cw(c627.45,1112.14) 634.81,1113.82 ; 626.42,1119.62 cw(c627.45,1112.14) 634.81,1113.82 ; 634.81,1113.82 cw(c605.61,1107.14) 635.12,1102.01 ; 634.81,1113.82 cw(c605.61,1107.14) 635.12,1102.01 ; 635.12,1102.01 ccw(c641.86,1100.84) 644.03,1094.35 cw(c641.86,1100.84) 635.12,1102.01 ; 540.25,1129.87 544.08,1132.46 540.25,1129.87 ; 542.21,1131.53 549.57,1135.57 542.21,1131.53
  text "PROC207 REVA" at 1000,3145 h40
  text "HOST_CLK_REQ" at 525.67,3029.88 h22 r90
  text "GPADC2" at 1856.21,3019.08 h25
  text "RADAR_OSC_CLKOUT" at 1777.46,2957.36 h25 r90
  text "GPADC1" at 1910.16,2925.05 h25
  text "RADAR_1V_RF_OUT" at 1385.9,2901.57 h25
  text "GPADC4" at 1788.35,2873.31 h25
  text "SPIB_CONN" at 240.72,2795.84 h25 r90
  text "GPADC3" at 1819.05,2744.39 h25
  text "RESET_OUT" at 389.4,2672.65 h22
  text "SCL" at 122.38,2625.38 h22
  text "I2C CONN" at 224.15,2532.15 h22 r90
  text "SDA" at 224.15,2431.38 h22 r90
  text "RTC_CLK_IN" at 1577.33,2429.87 h25 r90
  text "RX" at 763,2334.44 h25
  text "GND" at 844.13,2333.93 h25
  text "TX" at 657.58,2332.38 h25
  text "GND" at 113.86,2301.84 h22
  text "CAN_FD_L" at 19.8,2227 h20
  text "VPP_1P7" at 211.49,2200.6 h22 r90
  text "UARTB_CONN" at 740.47,2184.52 h25
  text "USER_SWITCH_1" at 780.52,2140.86 h25
  text "WU_REQ" at 1556.01,2073.37 h25 r90
  text "LVDS_VALID" at 2384.59,2044.44 h22
  text "GND" at 216.47,2022.7 h22 r90
  text "CAN_FD_CONN" at 249.88,1961.39 h22 r90
  text "VCC_3V3" at 3094.97,1960.54 h20
  text "USER_SWITCH_2" at 1960.57,1959.55 h22
  text "CAN_FD_H" at 15.67,1866.76 h20
  text "CAN_FD_B_L" at 18.43,1813.35 h20
  text "TX" at 801.92,1689.31 h25 r90
  text "PMIC_1V8" at 2362.22,1635.83 h20
  text "GND" at 212.47,1610.09 h20 r90
  text "RX" at 799.46,1587.61 h25 r90
  text "CAN_FD_B_CONN" at 247.54,1563.41 h22 r90
  text "GND" at 782.22,1498.54 h25
  text "CAN_FD_B_H" at 22.83,1456.5 h20
  text "FTDI_USB" at 3878.04,1443.33 h25
  text "UARTA" at 658.51,1424.69 h25
  text "XDS_I2C_SW" at 1266,1371.67 h22
  text "H/W TRG" at 449.8,1279.39 h25
  text "LIN_CONN" at 24.73,1217.44 h25
  text "PMIC_1V2" at 2673,1194.17 h25
  text "VSYS_IN" at 124.15,1180.65 h20
  text "PMIC_3V3" at 1556,1154.17 h25
  text "R" at 711.77,1123.63 h10
  text "MISTRAL" at 499.49,1035.61 h56.97
  text "RESET SWITCH" at 953.28,1009.03 h25
  text "DC 12V/5V" at 3830.7,1008.06 h25
  text "VSYS_IN" at 1990,1007.17 h25
  text "VBAT" at 172.85,973.88 h20
  text "VCC_12V" at 2899.55,907.03 h25
  text "LIN_BUS" at 185.1,878.21 h20
  text "FTDI SUSPEND" at 1870.71,864.57 h22
  text "5V_USB" at 3393.94,774.35 h25
  text "GND" at 123.94,770.71 h20
  text "PGOOD" at 2027.46,688.14 h20
  text "nERROR OUT LED" at 1002.36,631.57 h20
  text "FUNCTIONAL" at 327.23,602.9 h22
  text "MODE" at 378.58,564.14 h22
  text "VOUT_STS" at 2874.18,561.02 h22
  text "SOP1_H" at 738.84,559.44 h22
  text "PMIC_CLK_OUT" at 938.85,557.44 h20
  text "SOP0_H" at 82.26,555.64 h22
  text "XDS_3V3" at 3077.74,543.86 h25
  text "USER_LED_2" at 2837.4,524.81 h22
  text "USER LED 1" at 939.07,493.79 h22
  text "XDS_USB" at 3903.9,458.07 h25
  text "VSYS" at 2747.72,428.82 h22
  text "RESET_LED" at 1607.57,306.47 h25
  text "SOP0_L" at 78.38,252.5 h22
  text "SOP1_L" at 737.07,247.05 h22
  text "FLASHING" at 322.05,215.66 h22
  text "MODE" at 365.06,185.15 h22
  text "SPI_A_HEADER" at 1036.45,90.99 h25
  text "GND" at 2914.45,89.68 h25
  text ".Layer_Name" at 186.57,-874.24 h60
Bottom Overlay:
  circle w10: c2553.76,2946.77 r4.76
  circle w10: c1293.26,444.38 r4.76
  rectangle: 949.76,3328.69 1638.2,3426.93
  lines w6: 862,2069 839.71,2069 839.71,2151 815,2151 815,2218 900,2218 ; 1825,1972 1791.24,1972 1791.24,2202.68 1858,2202.68 ; 2190.1,1122.9 2225.98,1122.9 2225.98,1265 2199.77,1265
  lines w10: 949.76,3328.84 1775.94,3328.84 1775.94,3428.98 ; 949.76,3428.84 1775.94,3428.84 ; 950.31,3328.84 950.31,3428.84 ; 1638.2,3328.69 1638.2,3426.93
  text "SL#" at 1756.24,3360.13 h70
  text "FY24-25/01816000101" at 1608.89,3036.68 h25
  text "SPIB_CONN" at 62.65,2910.22 h25 r270
  text "I2C CONN" at 56.61,2391.27 h22 r270
  text "CAN_FD_CONN" at 70.52,1940.17 h22 r270
  text "CAN_FD_B_CONN" at 72.79,1515.58 h22 r270
  text "LP/BP CONN" at 2716.14,1444.14 h25
  text "3V3" at 570.26,1414.67 h60
  text "5V" at 938.98,1410.36 h60
  text "GND" at 2710.66,1356.14 h60
  text "CAUTION" at 1955.2,1263.09 h35
  text "HOT" at 1890.37,1209.37 h35
  text "SURFACE" at 1963.58,1157.13 h35
  text "LIN_CONN" at 68.27,880 h25 r270
  text "LP/BP CONN" at 879.99,386.39 h25
  text "DCA1000_CONN" at 2702.32,278.63 h25 r270
  text "SPI_A_HEADER" at 802.2,189.64 h25
  text "For evaluation only; not FCC approved for resale." at 2094,104 h45.3
  text "GND" at 2892.01,38.65 h25
  text ".Layer_Name" at 186.57,-874.24 h60
Top Paste:
  text ".Layer_Name" at 186.57,-874.24 h60
Bottom Paste:
  text ".Layer_Name" at 186.57,-874.24 h60
Top Solder:
  rectangle: 4082.25,2288.25 4094.49,3724.79
  region: 4094.49,3712.55 4094.49,3724.79 1808.97,3724.79 1808.97,3712.55
  region: 2382.93,2963.97 2394.02,2963.97 2394.02,2941.41 2382.93,2941.41
  region: 2343.56,2963.97 2354.65,2963.97 2354.65,2941.41 2343.56,2941.41
  region: 2304.19,2963.97 2315.28,2963.97 2315.28,2941.41 2304.19,2941.41
  region: 2264.82,2963.97 2275.91,2963.97 2275.91,2941.41 2264.82,2941.41
  region: 2225.45,2963.97 2236.54,2963.97 2236.54,2941.41 2225.45,2941.41
  region: 2186.08,2963.97 2197.17,2963.97 2197.17,2941.41 2186.08,2941.41
  region: 2146.71,2963.97 2157.8,2963.97 2157.8,2941.41 2146.71,2941.41
  region: 2107.34,2963.97 2118.43,2963.97 2118.43,2941.41 2107.34,2941.41
  region: 2478.59,2640.64 2478.59,2629.55 2458.48,2629.55 2458.48,2640.64
  region: 2478.59,2680.01 2478.59,2668.92 2458.48,2668.92 2458.48,2680.01
  region: 2478.59,2719.38 2478.59,2708.29 2458.48,2708.29 2458.48,2719.38
  region: 2478.59,2758.75 2478.59,2747.66 2458.48,2747.66 2458.48,2758.75
  region: 2478.59,2798.12 2478.59,2787.03 2458.48,2787.03 2458.48,2798.12
  region: 2478.59,2876.86 2478.59,2865.77 2458.48,2865.77 2458.48,2876.86
  region: 2478.59,2916.23 2478.59,2905.14 2458.48,2905.14 2458.48,2916.23
  region: 2478.59,2837.49 2478.59,2826.4 2458.48,2826.4 2458.48,2837.49
  text ".Layer_Name" at 186.57,-874.24 h60
  text ".Layer_Name" at 186.57,-874.24 h60
Bottom Solder:
  text ".Layer_Name" at 186.57,-874.24 h60
Drill Guide:
  text ".Layer_Name" at 186.57,-874.24 h60
M1 Board Outline:
  lines w5: 0,-78.74 0,-354.34 2479.33,-354.34 4094.49,-354.34 ; 0,-77.79 200,-77.79 ; 200,3803.53 0,3803.53 0,4079.13 688.98,4079.13 4094.49,4079.13 ; 470.87,-77.79 564.69,-77.79 ; 1341.21,-77.79 564.69,-77.79 ; 1612.07,-77.75 2882.42,-77.75 ; 3153.28,-77.75 3623.62,-77.75 ; 3153.28,3803.57 3623.62,3803.57 ; 3894.49,-77.75 4094.49,-77.75 ; 3894.49,3803.57 4094.49,3803.57 4094.49,4079.17 ; 4094.49,-354.38 4094.49,-78.78 ; 564.69,-77.79 564.69,-77.79 ; 0,0 2174.49,0 2174.49,381.95 2534.49,381.95 2534.49,0 4094.49,0 4094.49,3724.79 0,3724.79 0,0
  lines w6: 470.87,3803.53 1341.17,3803.53 ; 1612.07,3803.57 2482.42,3803.57 ; 2753.28,3803.57 3153.28,3803.57
  text ".Layer_Name" at 179.96,-797.55 h40
M2 Board Dimensions:
  text ".Layer_Name" at 174.69,-872.3 h60
M3 3D STEP Top:
  text ".Layer_Name" at 186.57,-874.24 h60
M4 3D STEP Bottom:
  circle w0.5: c-82.18,-626.47 r3.5
  text ".Layer_Name" at 186.57,-874.24 h60
M5 Assembly Top:
  lines w4: 222.13,2204.41 322.13,2204.41 322.13,2404.41 222.13,2404.41 222.13,2204.41
  lines w10: -682.43,-945.91 5917.57,-945.91 ; -682.43,-742.58 5919.57,-742.58 ; -682.43,-539.25 -682.43,-1149.25 3322.57,-1149.25 5919.57,-1149.25 5919.57,-539.25 -681.93,-539.25 -681.93,-1149.25 893.57,-1149.25 ; 1782.57,-1149.25 1782.57,-539.25 ; 3049.57,-742.58 3049.57,-539.25 ; 3889.57,-742.58 3889.57,-539.25 ; 4511.57,-1155.75 4511.57,-952.91
  text "COMPONENTS MARKED 'DNP' SHOULD NOT BE POPULATED." at 39.82,4288.04 h60
  text "ASSEMBLY VARIANT:" at 39.32,4172.54 h60
  text ".VariantName" at 1075.32,4172.54 h60
  text "PCB VIEWED FROM TOP SIDE" at -618.93,-671.41 h60
  text "BOARD #:" at 1857.57,-671.41 h60
  text ".PRJ_Number" at 2403.07,-671.41 h60
  text "REV:" at 3247.57,-671.41 h60
  text ".PCB_Rev" at 3539.07,-671.41 h60
  text "SVN REV:" at 4085.57,-671.41 h60
  text ".VersionControl_RevNumber" at 4591.57,-671.41 h60
  text "Assembly Layer Top" at 176.57,-870.75 h60
  text "TID #:" at 1857.57,-874.75 h60
  text ".TID" at 2403.07,-874.75 h60
  text "PLOT NAME =" at -618.93,-1080.08 h60
  text ".plot_File_Name" at 186.57,-1080.08 h60
  text "GENERATED    :" at 1859.57,-1080.08 h60
  text ".Print_Date" at 2729.07,-1080.08 h60
  text ".Print_Time" at 3458.07,-1080.08 h60
  text "TEXAS INSTRUMENTS" at 4722.57,-1080.08 h60
M6 Assembly Bottom:
  lines w4: 2194.03,1269.24 2218.48,1269.24 ; 2207.72,1258.48 2218.48,1269.24 ; 2207.72,1280 2218.48,1269.24
  lines w10: -682.93,-743.08 5919.07,-743.08 ; -680.93,-946.41 5919.07,-946.41 ; 725.07,-1156.25 725.07,-953.41 ; 1347.07,-743.08 1347.07,-539.75 ; 2187.07,-743.08 2187.07,-539.75 ; 3454.07,-1149.75 3454.07,-539.75 ; 4343.07,-1149.75 5918.57,-1149.75 5918.57,-539.75 -682.93,-539.75 -682.93,-1149.75 1914.07,-1149.75 5919.07,-1149.75 5919.07,-539.75
  text "COMPONENTS MARKED 'DNP' SHOULD NOT BE POPULATED." at 5916.15,-316.7 h60
  text ".VariantName" at 4872.15,-432.7 h60
  text "ASSEMBLY VARIANT:" at 5911.15,-432.7 h60
  text ".VersionControl_RevNumber" at 645.07,-671.91 h60
  text "SVN REV:" at 1151.07,-671.91 h60
  text ".PCB_Rev" at 1697.57,-671.91 h60
  text "REV:" at 1989.07,-671.91 h60
  text ".PRJ_Number" at 2833.57,-671.91 h60
  text "BOARD #:" at 3379.07,-671.91 h60
  text "PCB VIEWED FROM BOTTOM SIDE" at 5855.57,-671.91 h60
  text "Assembly Bottom Layer" at 5494.57,-860.75 h60
  text ".TID" at 2833.57,-875.25 h60
  text "TID #:" at 3379.07,-875.25 h60
  text "TEXAS INSTRUMENTS" at 514.07,-1080.58 h60
  text ".Print_Time" at 1778.57,-1080.58 h60
  text ".Print_Date" at 2507.57,-1080.58 h60
  text "GENERATED    :" at 3377.07,-1080.58 h60
  text ".plot_File_Name" at 5050.07,-1080.58 h60
  text "PLOT NAME =" at 5855.57,-1080.58 h60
